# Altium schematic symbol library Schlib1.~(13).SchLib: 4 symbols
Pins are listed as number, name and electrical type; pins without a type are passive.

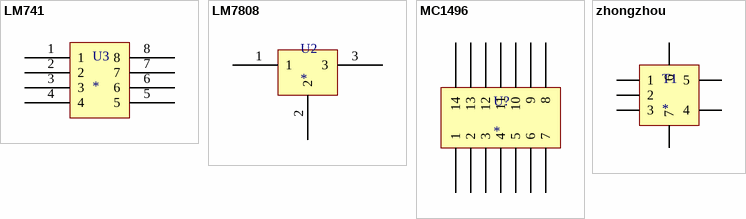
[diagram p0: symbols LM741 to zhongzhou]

## LM741
designator U3
pins: 1, 2, 3, 4, 5, 6, 7, 8

## LM7808
designator U2
pins: 1, 2, 3

## MC1496
designator U?
pins: 1, 2, 3, 4, 5, 6, 7, 8, 9, 10, 11, 12, 13, 14

## zhongzhou
designator T1
pins: 1, 2, 3, 4, 5, 6, 7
